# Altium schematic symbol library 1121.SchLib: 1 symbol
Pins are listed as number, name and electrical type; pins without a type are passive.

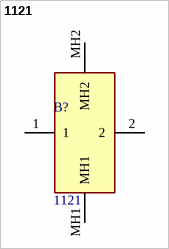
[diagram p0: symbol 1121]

## 1121
designator B?
Cylindrical Battery Contacts, Clips, Holders & Springs THM BATTERY HOLDER FOR 20700 & 21700; Manufacturer_Name: Keystone Electronics; Geometry.Height: 17.27mm
footprint 1121
pins: 1, 2, MH1, MH2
